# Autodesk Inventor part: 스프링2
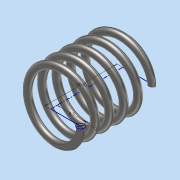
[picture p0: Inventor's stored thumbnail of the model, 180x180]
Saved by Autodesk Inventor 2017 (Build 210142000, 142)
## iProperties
Part Number: 스프링2
Material: 스테인레스 스틸
Document SubType Name: Modeling
Designer: MRC
Density: 8 g/cm^3
Appearance: 반연마
Mass: 6.57245 g
Surface Area: 16.7217 cm^2
Volume: 0.821556 cm^3
Author: MRC
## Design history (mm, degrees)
sketch "스케치1"
  geometry: L1 (0, 0)-(0, 20.5); L2 (0, 0)-(8.5, 0); L3 (0, 20.5)-(8.5, 20.5); C1 r 1 at (8.5, 0)
  constraints: 6 end point, 2 horizontal, 1 centre point, 1 coincident, 1 vertical
  dimensions: "d0" = 20.5 distance of L1.start L1.end (derived); "d1" = 8.5 distance of L1.start L2.end; "d2" = 2 diameter of C1
feature "코일1" pitch "d3" = 10; turns "d5" = 5; dims "d4" = 20.5 (= d0), "d6" = 0, angle "d7" = 90 deg, angle "d8" = 90 deg, "d9" = 0, "d10" = 0
sketch "스케치2"
  geometry: L1 (20.5, 13.489)-(0, 13.489); L2 (0, 13.489)-(0, -13.489); L3 (0, -13.489)-(20.5, -13.489); L4 (20.5, -13.489)-(20.5, 13.489); 2 further points
  constraints: 8 end point, 2 parallel, 1 coincident, 1 horizontal, 1 midpoint, 1 perpendicular
  dimensions: "d11" = 20.5 distance of L2.end L3.end (= d0)
extrude "돌출1" sketch "스케치2" stored distance "d12" = 0; taper "d13" = 0 deg
node "솔리드1"
